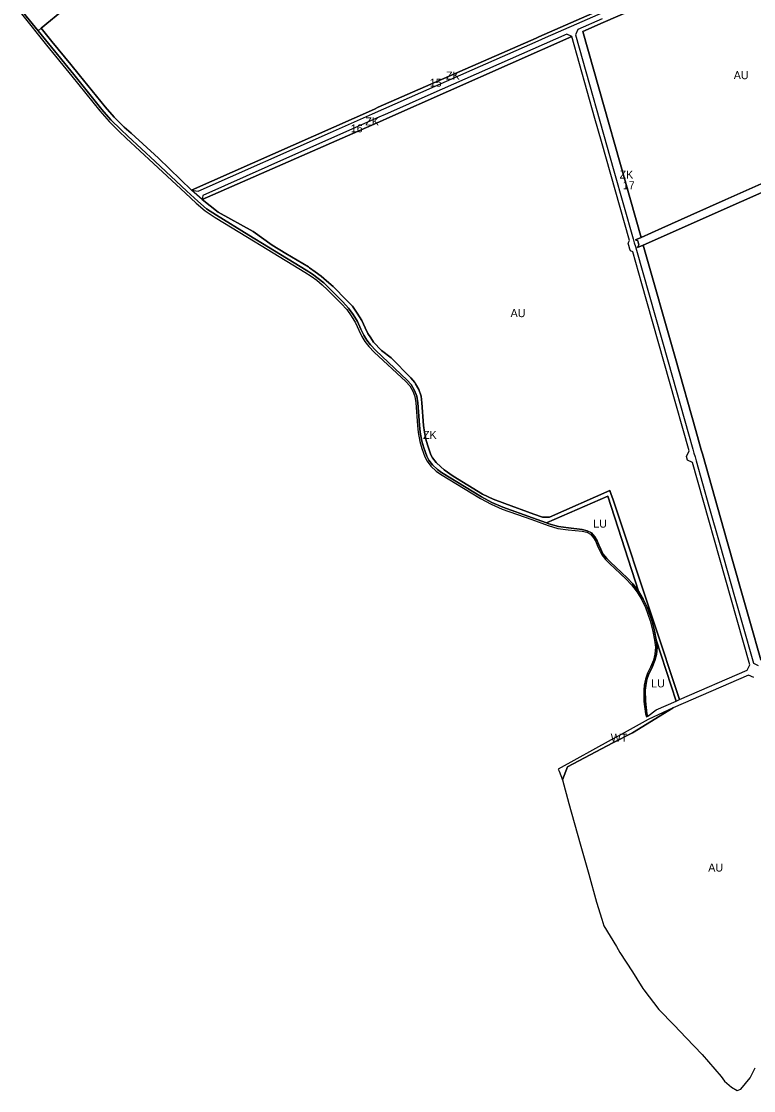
# Model space of a CAD drawing. Extents: x -522079 to -518833, y -1142398 to -1139961.
# Drawn here: x -521918 to -521003, y -1142398 to -1141061 of the extents above; entities that cross this region are included whole.
import ezdxf

# ---------------------------------------------------------------- set-up
doc = ezdxf.new("R2010")
doc.units = 0
for name, color, linetype in [('90640013', 7, 'Continuous'), ('90710013', 7, 'Continuous'), ('90710023', 7, 'Continuous'), ('90730023', 7, 'Continuous'), ('90750013', 7, 'Continuous'), ('90770013', 7, 'Continuous'), ('ID_navrh', 7, 'Continuous')]:
    doc.layers.add(name, color=color, linetype=linetype)

msp = doc.modelspace()

# ---------------------------------------------------------------- linework, layer by layer
at = {"layer": '90640013'}
msp.add_lwpolyline([(-521917.71, -1141051.91), (-521886.17, -1141090.77), (-521854.62, -1141129.62), (-521819.49, -1141173.11), (-521808.03, -1141186.29), (-521795.61, -1141198.73), (-521786.69, -1141207.07), (-521752.44, -1141238.81), (-521712.83, -1141275.84), (-521699.37, -1141288.32), (-521688.05, -1141297.92), (-521675.66, -1141306.27), (-521635.13, -1141330.98), (-521610.54, -1141345.88), (-521563.41, -1141374.64), (-521555.61, -1141379.71), (-521548.66, -1141384.81), (-521541.97, -1141390.39), (-521535.13, -1141396.73), (-521518.22, -1141413.8), (-521511.22, -1141421.52), (-521505.54, -1141429.29), (-521500.39, -1141437.89), (-521496.24, -1141447.12), (-521492.43, -1141454.93), (-521488.42, -1141461.33), (-521483.59, -1141467.79), (-521476.9, -1141474.65), (-521437.41, -1141511.31), (-521432.52, -1141516.64), (-521428.59, -1141523.58), (-521425.94, -1141530.31), (-521424.81, -1141537.99), (-521422.84, -1141566.15), (-521421.99, -1141574.92), (-521419.85, -1141586.36), (-521417.34, -1141595.15), (-521413.41, -1141605.57), (-521410.67, -1141610.84), (-521405.95, -1141617.2), (-521399.42, -1141623.32), (-521394.19, -1141627.12), (-521344.1, -1141657.73), (-521330.81, -1141664.89), (-521317.08, -1141670.75), (-521280.03, -1141684.05), (-521259.69, -1141691.44), (-521247.24, -1141694.95), (-521234.47, -1141696.96), (-521216.85, -1141698.47), (-521211.3, -1141699.75), (-521206.66, -1141702.29), (-521202.67, -1141706.57), (-521199.97, -1141711.28), (-521198.13, -1141716.1), (-521195.55, -1141722.03), (-521192.28, -1141728.07), (-521187.74, -1141733.86), (-521183.03, -1141738.83), (-521162.29, -1141758.22), (-521155.26, -1141765.5), (-521148.13, -1141774.78), (-521142.46, -1141784.23), (-521137.85, -1141793.99), (-521131.96, -1141810.32), (-521128.54, -1141823.8), (-521126.47, -1141834.73), (-521125.45, -1141843.51), (-521126.1, -1141852.28), (-521127.98, -1141859.55), (-521131.82, -1141868.6), (-521135.49, -1141876.13), (-521138.03, -1141883.29), (-521139.56, -1141890.84), (-521140.05, -1141897.31), (-521139.81, -1141911.29), (-521137.86, -1141926.67), (-521136.46, -1141930.46), (-521135.11, -1141929.87), (-521136.31, -1141926.58), (-521137.83, -1141911.01), (-521138.09, -1141897.36), (-521137.56, -1141891.19), (-521136.12, -1141883.81), (-521133.7, -1141876.9), (-521130.11, -1141869.48), (-521126.12, -1141860.01), (-521124.12, -1141852.65), (-521123.46, -1141843.47), (-521124.58, -1141834.32), (-521126.54, -1141823.43), (-521130, -1141809.79), (-521136, -1141793.25), (-521140.73, -1141783.35), (-521146.44, -1141773.64), (-521153.73, -1141764.26), (-521160.88, -1141756.78), (-521181.74, -1141737.31), (-521186.22, -1141732.52), (-521191.06, -1141726.58), (-521193.87, -1141721.1), (-521196.27, -1141715.36), (-521198.1, -1141710.58), (-521201.07, -1141705.38), (-521205.36, -1141700.71), (-521210.58, -1141697.9), (-521216.85, -1141696.44), (-521234.23, -1141694.42), (-521246.75, -1141692.49), (-521258.87, -1141689.08), (-521261.42, -1141688.16), (-521279.18, -1141681.72), (-521315.94, -1141668.52), (-521329.77, -1141662.64), (-521342.84, -1141655.56), (-521392.9, -1141624.99), (-521397.79, -1141621.36), (-521404.06, -1141615.52), (-521408.6, -1141609.5), (-521411.13, -1141604.62), (-521415, -1141594.31), (-521417.39, -1141585.84), (-521419.55, -1141574.63), (-521420.36, -1141565.98), (-521422.3, -1141537.87), (-521423.45, -1141529.64), (-521426.4, -1141522.52), (-521430.56, -1141515.15), (-521435.7, -1141509.5), (-521474.82, -1141472.48), (-521481.44, -1141465.72), (-521485.96, -1141459.56), (-521489.81, -1141453.49), (-521493.43, -1141445.97), (-521497.72, -1141436.55), (-521503.06, -1141427.66), (-521508.94, -1141419.63), (-521516.02, -1141411.74), (-521532.97, -1141394.62), (-521539.97, -1141388.19), (-521546.79, -1141382.47), (-521553.85, -1141377.26), (-521561.83, -1141372.1), (-521608.95, -1141343.32), (-521633.59, -1141328.38), (-521674.08, -1141303.65), (-521686.23, -1141295.55), (-521697.27, -1141286.12), (-521710.79, -1141273.6), (-521750.42, -1141236.56), (-521784.67, -1141204.85), (-521793.6, -1141196.53), (-521805.87, -1141184.18), (-521817.11, -1141171.17), (-521852.32, -1141127.72), (-521883.81, -1141088.91), (-521896.82, -1141072.9), (-521915.45, -1141049.99)], dxfattribs=at)
msp.add_lwpolyline([(-521241.65, -1142009.35), (-521235.48, -1141993.03), (-521178.81, -1141962.98), (-521154.29, -1141950.51), (-521103.17, -1141919.44), (-521134.44, -1141933.97), (-521171.94, -1141954.7), (-521180.62, -1141959.39), (-521247.07, -1141995.86), (-521245.74, -1141998.54)], close=True, dxfattribs=at)
at = {"layer": '90710013'}
for points in [[(-521705, -1141272.16), (-521746.52, -1141232.38), (-521780.54, -1141201.02), (-521789.46, -1141193.57), (-521801.69, -1141180.84), (-521813.1, -1141167.95), (-521845.59, -1141127.96), (-521855.85, -1141115.33), (-521879.49, -1141086.24), (-521893.06, -1141069.8), (-521896.82, -1141072.9), (-521883.81, -1141088.91), (-521852.32, -1141127.72), (-521817.11, -1141171.17), (-521805.87, -1141184.18), (-521793.6, -1141196.53), (-521784.67, -1141204.85), (-521750.42, -1141236.56), (-521710.79, -1141273.6), (-521697.27, -1141286.12), (-521686.23, -1141295.55), (-521674.08, -1141303.65), (-521633.59, -1141328.38), (-521608.95, -1141343.32), (-521561.83, -1141372.1), (-521553.85, -1141377.26), (-521546.79, -1141382.47), (-521539.97, -1141388.19), (-521532.97, -1141394.62), (-521516.02, -1141411.74), (-521508.94, -1141419.63), (-521503.06, -1141427.66), (-521497.72, -1141436.55), (-521493.43, -1141445.97), (-521489.81, -1141453.49), (-521485.96, -1141459.56), (-521481.44, -1141465.72), (-521474.82, -1141472.48), (-521435.7, -1141509.5), (-521430.56, -1141515.15), (-521426.4, -1141522.52), (-521423.45, -1141529.64), (-521422.3, -1141537.87), (-521420.36, -1141565.98), (-521419.55, -1141574.63), (-521417.39, -1141585.84), (-521415, -1141594.31), (-521411.13, -1141604.62), (-521408.6, -1141609.5), (-521404.06, -1141615.52), (-521397.79, -1141621.36), (-521392.9, -1141624.99), (-521342.84, -1141655.56), (-521329.77, -1141662.64), (-521315.94, -1141668.52), (-521279.18, -1141681.72), (-521261.42, -1141688.16), (-521185.06, -1141654.56), (-521146.44, -1141773.64), (-521140.73, -1141783.35), (-521136, -1141793.25), (-521130, -1141809.79), (-521126.54, -1141823.43), (-521124.58, -1141834.32), (-521099.58, -1141911), (-521095.32, -1141908.99), (-521128.33, -1141809.83), (-521178.83, -1141658.1), (-521180.65, -1141652.62), (-521182.3, -1141647.66), (-521257.85, -1141680.84), (-521266.74, -1141680.79), (-521277.4, -1141677.06), (-521313.67, -1141663.71), (-521328.02, -1141658.46), (-521341.44, -1141652.02), (-521378.39, -1141629.5), (-521389.3, -1141621.72), (-521393.54, -1141617.98), (-521399.61, -1141612.42), (-521404.05, -1141606.86), (-521406.05, -1141602.85), (-521409.49, -1141593.05), (-521412.01, -1141585.06), (-521414.13, -1141574.69), (-521415.34, -1141566.3), (-521417.47, -1141538.2), (-521418.07, -1141529.55), (-521421, -1141521.26), (-521425.07, -1141514.17), (-521426.04, -1141512.48), (-521431.09, -1141506.63), (-521455.62, -1141481.81), (-521467.85, -1141472.41), (-521477.75, -1141461.99), (-521481.18, -1141456.84), (-521484.69, -1141451.44), (-521488.03, -1141444.36), (-521492.17, -1141435.06), (-521498.23, -1141425.96), (-521504.19, -1141417.07), (-521511.47, -1141409.59), (-521528.31, -1141392.77), (-521536.29, -1141385.49), (-521543.06, -1141379.52), (-521550.74, -1141374.27), (-521557.71, -1141369.1), (-521558.92, -1141368.2), (-521587.36, -1141351.16), (-521604.24, -1141340.75), (-521628.15, -1141324.02), (-521671.77, -1141299.69), (-521692.02, -1141284.07), (-521705, -1141272.16)], [(-520895.96, -1141221.04), (-521038.45, -1141284.46), (-521081.35, -1141303.56), (-521117.38, -1141319.6), (-521143.42, -1141331.19), (-521150.33, -1141334.27), (-521147.33, -1141335.67), (-521146.08, -1141340.6), (-521147.68, -1141344.03), (-521140.66, -1141340.91), (-520895.18, -1141231.65)]]:
    msp.add_lwpolyline(points, dxfattribs=at)
at = {"layer": '90710023'}
for points in [[(-521134.23, -1141020.21), (-521271.3, -1141080.74), (-521274.53, -1141082.16), (-521472.07, -1141168.66), (-521476.67, -1141170.91), (-521705, -1141272.16), (-521696.71, -1141273.51), (-521531.28, -1141200.09), (-521478.81, -1141176.87), (-521464.85, -1141170.68), (-521354.37, -1141121.84), (-521271.86, -1141085.49), (-521262.72, -1141081.47), (-521223.67, -1141064.26), (-521134.18, -1141024.63), (-521134.23, -1141020.21)], [(-520993.82, -1141859.25), (-521007.52, -1141810.87), (-521017.38, -1141776.07), (-521035.75, -1141711.23), (-521066.79, -1141601.67), (-521068.18, -1141596.78), (-521074.97, -1141572.8), (-521100.48, -1141482.76), (-521140.66, -1141340.91), (-521147.68, -1141344.03), (-521146.08, -1141340.6), (-521147.33, -1141335.67), (-521150.33, -1141334.27), (-521143.42, -1141331.19), (-521216.29, -1141073.97), (-521190.59, -1141062.63), (-521154.28, -1141046.62)], [(-521191.96, -1141057.88), (-521222.3, -1141071.25), (-521225.53, -1141078.04), (-521177.35, -1141247.92), (-521153.24, -1141332.9), (-521151.86, -1141337.89), (-521150.52, -1141342.71), (-521149.23, -1141347.36), (-521109.72, -1141486.85), (-521084.21, -1141576.91), (-521078.78, -1141596.05), (-521077.42, -1141600.82), (-521076.03, -1141605.72), (-521074.66, -1141610.52), (-521058.67, -1141667), (-521044.98, -1141715.3), (-521026.62, -1141780.12), (-521016.76, -1141814.92), (-521003.04, -1141863.38), (-520997.06, -1141866.15)]]:
    msp.add_lwpolyline(points, dxfattribs=at)
msp.add_lwpolyline([(-521692.02, -1141284.07), (-521466.3, -1141184.96), (-521461.21, -1141182.74), (-521230.09, -1141080.11), (-521236.08, -1141077.32), (-521405.94, -1141152.24), (-521460.33, -1141176.23), (-521474.13, -1141182.35), (-521609.81, -1141242.59), (-521691.15, -1141278.7)], close=True, dxfattribs=at)
at = {"layer": '90730023'}
for points in [[(-521915.45, -1141049.99), (-521896.82, -1141072.9), (-521893.06, -1141069.8)], [(-521893.06, -1141069.8), (-521862.5, -1141044.56)]]:
    msp.add_lwpolyline(points, dxfattribs=at)
at = {"layer": '90750013'}
for points in [[(-520727.16, -1141148.38), (-520733.88, -1141082.24), (-520846.14, -1141104.23), (-520847.24, -1141100.33), (-520861.45, -1141049.84), (-520872.93, -1141009.05), (-520881.52, -1140979.72), (-520885.58, -1140965.84), (-520888.93, -1140954.41), (-520892.3, -1140942.89), (-520959.78, -1140968.46), (-520964.29, -1140970.32), (-521085.77, -1141016.42), (-521111.47, -1141027.75), (-521154.28, -1141046.62), (-521190.59, -1141062.63), (-521216.29, -1141073.97), (-521143.42, -1141331.19), (-521117.38, -1141319.6), (-521081.35, -1141303.56), (-521038.45, -1141284.46), (-520895.96, -1141221.04), (-520890.16, -1141218.54)], [(-521692.02, -1141284.07), (-521671.77, -1141299.69), (-521628.15, -1141324.02), (-521604.24, -1141340.75), (-521587.36, -1141351.16), (-521558.92, -1141368.2), (-521557.71, -1141369.1), (-521550.74, -1141374.27), (-521543.06, -1141379.52), (-521536.29, -1141385.49), (-521528.31, -1141392.77), (-521511.47, -1141409.59), (-521504.19, -1141417.07), (-521498.23, -1141425.96), (-521492.17, -1141435.06), (-521488.03, -1141444.36), (-521484.69, -1141451.44), (-521481.18, -1141456.84), (-521477.75, -1141461.99), (-521467.85, -1141472.41), (-521455.62, -1141481.81), (-521431.09, -1141506.63), (-521426.04, -1141512.48), (-521425.07, -1141514.17), (-521421, -1141521.26), (-521418.07, -1141529.55), (-521417.47, -1141538.2), (-521415.34, -1141566.3), (-521414.13, -1141574.69), (-521412.01, -1141585.06), (-521409.49, -1141593.05), (-521406.05, -1141602.85), (-521404.05, -1141606.86), (-521399.61, -1141612.42), (-521393.54, -1141617.98), (-521389.3, -1141621.72), (-521378.39, -1141629.5), (-521341.44, -1141652.02), (-521328.02, -1141658.46), (-521313.67, -1141663.71), (-521277.4, -1141677.06), (-521266.74, -1141680.79), (-521257.85, -1141680.84), (-521182.3, -1141647.66), (-521180.65, -1141652.62), (-521178.83, -1141658.1), (-521128.33, -1141809.83), (-521095.32, -1141908.99), (-521010.77, -1141872.32), (-521007.67, -1141865.49), (-521031.39, -1141781.75), (-521079.3, -1141612.54), (-521085.26, -1141609.76), (-521086.66, -1141604.9), (-521083.41, -1141598.05), (-521107.96, -1141511.35), (-521142.48, -1141389.44), (-521153.82, -1141349.39), (-521156.76, -1141348.04), (-521157.35, -1141345.97), (-521158.68, -1141341.24), (-521159.51, -1141338.32), (-521157.91, -1141334.94), (-521192.96, -1141211.21), (-521201.01, -1141182.77), (-521230.09, -1141080.11), (-521461.21, -1141182.74), (-521466.3, -1141184.96)], [(-520993.82, -1141859.25), (-520890.85, -1141813.79), (-520878.55, -1141754.38), (-520869.65, -1141711.4), (-520852.89, -1141630.48), (-520824.63, -1141494.01), (-520822.47, -1141493.04), (-520819.82, -1141495.44), (-520821.3, -1141482.16), (-520824.28, -1141488.21), (-520824.77, -1141488.43), (-520831.3, -1141464.59), (-520856.02, -1141374.46), (-520895.18, -1141231.65), (-521140.66, -1141340.91), (-521100.48, -1141482.76), (-521074.97, -1141572.8), (-521068.18, -1141596.78), (-521066.79, -1141601.67), (-521035.75, -1141711.23), (-521017.38, -1141776.07), (-521007.52, -1141810.87)]]:
    msp.add_lwpolyline(points, close=True, dxfattribs=at)
for points in [[(-521862.5, -1141044.56), (-521893.06, -1141069.8), (-521879.49, -1141086.24), (-521855.85, -1141115.33), (-521845.59, -1141127.96), (-521813.1, -1141167.95), (-521801.69, -1141180.84), (-521789.46, -1141193.57), (-521780.54, -1141201.02), (-521746.52, -1141232.38), (-521705, -1141272.16), (-521476.67, -1141170.91), (-521472.07, -1141168.66), (-521274.53, -1141082.16), (-521271.3, -1141080.74), (-521134.23, -1141020.21)], [(-521002.46, -1141881.16), (-521009, -1141878.54), (-521103.17, -1141919.44), (-521154.29, -1141950.51), (-521178.81, -1141962.98), (-521235.48, -1141993.03), (-521241.65, -1142009.35), (-521233.47, -1142038.91), (-521226.84, -1142062.52), (-521218.49, -1142092.03), (-521208.63, -1142126.99), (-521198.94, -1142162.11), (-521192.34, -1142183.35), (-521189.97, -1142191.57), (-521174.19, -1142217.64), (-521169.79, -1142225.11), (-521154.1, -1142249.25), (-521148.58, -1142258.19), (-521141.26, -1142270.03), (-521140.11, -1142271.9), (-521121.26, -1142296.3), (-521102.18, -1142315.9), (-521086.87, -1142331.63), (-521067.07, -1142352.38), (-521043.28, -1142380.16), (-521039.1, -1142385.71), (-521030.26, -1142393.33), (-521023.14, -1142397.72), (-521018.9, -1142395.87), (-521007.1, -1142381.81), (-521000.81, -1142369.28)]]:
    msp.add_lwpolyline(points, dxfattribs=at)
at = {"layer": '90770013'}
for points in [[(-521146.44, -1141773.64), (-521185.06, -1141654.56), (-521261.42, -1141688.16), (-521258.87, -1141689.08), (-521246.75, -1141692.49), (-521234.23, -1141694.42), (-521216.85, -1141696.44), (-521210.58, -1141697.9), (-521205.36, -1141700.71), (-521201.07, -1141705.38), (-521198.1, -1141710.58), (-521196.27, -1141715.36), (-521193.87, -1141721.1), (-521191.06, -1141726.58), (-521186.22, -1141732.52), (-521181.74, -1141737.31), (-521160.88, -1141756.78), (-521153.73, -1141764.26), (-521146.44, -1141773.64)], [(-521099.58, -1141911), (-521124.58, -1141834.32), (-521123.46, -1141843.47), (-521124.12, -1141852.65), (-521126.12, -1141860.01), (-521130.11, -1141869.48), (-521133.7, -1141876.9), (-521136.12, -1141883.81), (-521137.56, -1141891.19), (-521138.09, -1141897.36), (-521137.83, -1141911.01), (-521136.31, -1141926.58), (-521135.11, -1141929.87), (-521124.47, -1141921.72), (-521099.58, -1141911)]]:
    msp.add_lwpolyline(points, dxfattribs=at)

# ---------------------------------------------------------------- texts
at = {"layer": '90640013'}
msp.add_text('WT', height=10, rotation=0, dxfattribs=at).set_placement((-521181.3, -1141961.65))
at = {"layer": '90710013'}
msp.add_text('ZK', height=10, rotation=360, dxfattribs=at).set_placement((-521415.9, -1141583.16))
at = {"layer": '90710023'}
for rotation, p in [(0, (-521387.15, -1141134.01)), (0, (-521487.98, -1141191.36)), (360, (-521170.28, -1141257.72))]:
    msp.add_text('ZK', height=10, rotation=rotation, dxfattribs=at).set_placement(p)
at = {"layer": '90750013'}
for rotation, p in [(360, (-521027.61, -1141133.45)), (0, (-521306.48, -1141430.89)), (0, (-521059.53, -1142123.92))]:
    msp.add_text('AU', height=10, rotation=rotation, dxfattribs=at).set_placement(p)
at = {"layer": '90770013'}
for p in [(-521203.15, -1141694.01), (-521130.81, -1141893.72)]:
    msp.add_text('LU', height=10, rotation=360, dxfattribs=at).set_placement(p)
at = {"layer": 'ID_navrh'}
for s, rotation, p in [('15', 0, (-521407.43, -1141142.84)), ('16', 360, (-521506.13, -1141199.95)), ('17', 360, (-521166.25, -1141271.01))]:
    msp.add_text(s, height=10, rotation=rotation, dxfattribs=at).set_placement(p)

doc.saveas('drawing.dxf')
